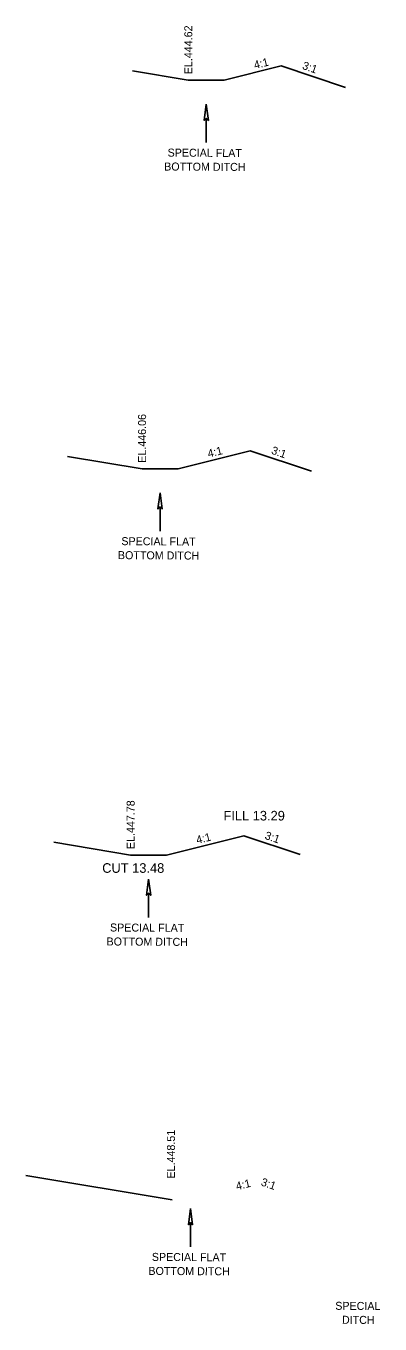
# Model space of a CAD drawing. Extents: x 37 to 1710, y 707 to 2305.
# Drawn here: x 918.9 to 963.2, y 1559.2 to 1721.4 of the extents above; entities that cross this region are included whole.
import ezdxf

# ---------------------------------------------------------------- set-up
doc = ezdxf.new("R2010")
doc.units = 0
for name, color, linetype in [('DESIGN - DRAINAGE - Special Ditch Width Text', 7, 'Continuous'), ('DESIGN - DRAINAGE - Text', 7, 'Continuous'), ('DESIGN - TYPICAL - Finished Grade and Subgrade', 7, 'Continuous'), ('DESIGN - TYPICAL - Finished Grade Slopes Text', 7, 'Continuous'), ('DESIGN - TYPICAL - Text', 7, 'Continuous')]:
    doc.layers.add(name, color=color, linetype=linetype)

msp = doc.modelspace()

# ---------------------------------------------------------------- linework, layer by layer
at = {"layer": 'DESIGN - DRAINAGE - Special Ditch Width Text'}
for p, q in [((941.48, 1709.86), (941.48, 1706.85)), ((935.7, 1661.3), (935.7, 1658.28)), ((934.27, 1613.02), (934.27, 1610)), ((939.51, 1571.85), (939.51, 1568.83))]:
    msp.add_line(p, q, dxfattribs=at)
for points in [[(941.48, 1711.62), (941.74, 1709.6), (941.48, 1709.86), (941.22, 1709.6)], [(935.7, 1663.06), (935.96, 1661.04), (935.7, 1661.3), (935.44, 1661.04)], [(934.27, 1614.78), (934.53, 1612.76), (934.27, 1613.02), (934.01, 1612.76)], [(939.51, 1573.61), (939.77, 1571.59), (939.51, 1571.85), (939.25, 1571.59)]]:
    msp.add_lwpolyline(points, close=True, dxfattribs=at)
for points in [[(941.48, 1711.62), (941.74, 1709.6), (941.48, 1709.86), (941.22, 1709.6), (941.48, 1711.62)], [(935.7, 1663.06), (935.96, 1661.04), (935.7, 1661.3), (935.44, 1661.04), (935.7, 1663.06)], [(934.27, 1614.78), (934.53, 1612.76), (934.27, 1613.02), (934.01, 1612.76), (934.27, 1614.78)], [(939.51, 1573.61), (939.77, 1571.59), (939.51, 1571.85), (939.25, 1571.59), (939.51, 1573.61)]]:
    msp.add_lwpolyline(points, dxfattribs=at)
at = {"layer": 'DESIGN - TYPICAL - Finished Grade and Subgrade'}
for p, q in [((943.73, 1714.62), (950.86, 1716.41)), ((950.86, 1716.41), (958.89, 1713.73)), ((932.24, 1715.79), (939.23, 1714.62)), ((939.23, 1714.62), (943.73, 1714.62)), ((937.95, 1666.06), (946.98, 1668.32)), ((946.98, 1668.32), (954.64, 1665.77)), ((924.14, 1667.61), (933.45, 1666.06)), ((933.45, 1666.06), (937.95, 1666.06)), ((922.4, 1619.38), (932.02, 1617.78)), ((936.52, 1617.78), (946.16, 1620.19)), ((946.16, 1620.19), (953.23, 1617.84)), ((932.02, 1617.78), (936.52, 1617.78)), ((918.93, 1577.76), (937.2, 1574.71))]:
    msp.add_line(p, q, dxfattribs=at)

# ---------------------------------------------------------------- texts
at = {"layer": 'DESIGN - DRAINAGE - Special Ditch Width Text'}
for s, p in [('SPECIAL FLAT', (936.64, 1705.08)), ('BOTTOM DITCH', (936.21, 1703.34)), ('SPECIAL FLAT', (930.86, 1656.52)), ('BOTTOM DITCH', (930.43, 1654.77)), ('SPECIAL FLAT', (929.44, 1608.24)), ('BOTTOM DITCH', (929.01, 1606.49)), ('SPECIAL FLAT', (934.67, 1567.07)), ('BOTTOM DITCH', (934.24, 1565.32)), ('SPECIAL ', (957.6, 1560.96)), ('DITCH', (958.44, 1559.21))]:
    msp.add_text(s, height=1, rotation=359.6675, dxfattribs=at).set_placement(p)
at = {"layer": 'DESIGN - DRAINAGE - Text'}
for s, p in [('EL.444.62', (939.73, 1715.37)), ('EL.446.06', (933.95, 1666.81)), ('EL.447.78', (932.52, 1618.53)), ('EL.448.51', (937.56, 1577.36))]:
    msp.add_text(s, height=1, rotation=90, dxfattribs=at).set_placement(p)
at = {"layer": 'DESIGN - TYPICAL - Finished Grade Slopes Text'}
for s, rotation, p in [('4:1', 14.0362, (947.56, 1716.01)), ('3:1', 340.7552, (953.4, 1716.06)), ('4:1', 14.0362, (941.78, 1667.45)), ('3:1', 340.7552, (949.53, 1667.97)), ('3:1', 340.7552, (948.71, 1619.84)), ('4:1', 14.0362, (940.35, 1619.17)), ('4:1', 14.0362, (945.31, 1575.9)), ('3:1', 340.7552, (948.23, 1576.53))]:
    msp.add_text(s, height=1, rotation=rotation, dxfattribs=at).set_placement(p)
at = {"layer": 'DESIGN - TYPICAL - Text'}
for s, p in [('FILL 13.29', (943.63, 1622.11)), ('CUT 13.48', (928.47, 1615.57))]:
    msp.add_text(s, height=1.2, dxfattribs=at).set_placement(p)

doc.saveas('drawing.dxf')
